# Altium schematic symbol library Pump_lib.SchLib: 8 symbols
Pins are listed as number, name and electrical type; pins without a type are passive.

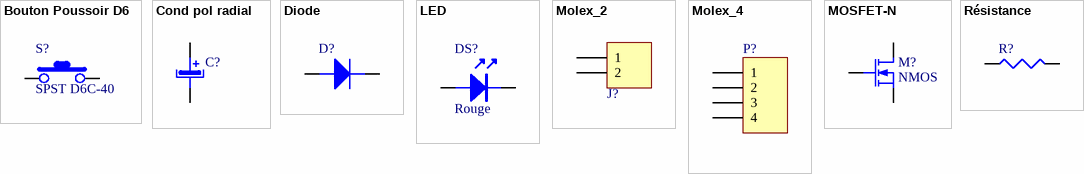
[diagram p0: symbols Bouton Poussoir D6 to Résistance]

## Bouton Poussoir D6
designator S?  Type: SPST D6C-40
Bouton poussoir; Manufacturer: ITT CANON
footprint BP-D6 SPST (Footprint not found)
pins: 1, 2

## Cond pol radial
designator C?
Condensateur polatisé; Type: Condensateur polarisé debout
footprint CAPPR1.27-1.7x2.8 (Capacitor, Radial, Tantalum; Body 1.7 x 2.8 mm (Dia.xH max); Pin Spacing 1.27 mm (typ))
footprint CAPPR1.5-4x5 (Capacitor, Electrolytic, Radial; Body 4 x 5 mm (Dia.xH typ); Pin Spacing 1.5 mm (typ))
footprint CAPPR2-5x6.8 (Capacitor, Electrolytic, Radial; Body 5 x 6.8 mm (Dia.xH typ); Pin Spacing 2 mm (typ))
footprint CAPPR5-5x5 (Capacitor, Electrolytic, Radial; Body 5 x 5 mm (Dia.xH typ); Pin Spacing 5 mm (typ))
footprint CAPPR7.5-16x35 (Capacitor, Electrolytic, Radial; Body 16 x 35 mm (Dia.xH typ); Pin Spacing 7.5 mm (typ))
pins: 1 +, 2 -
2 alternate drawings of the same symbol

## Diode
designator D?
Diode; Type: Diode standard
simulation model DIODE (Diode)
footprint DIO7.1-3.9x1.9 (Diode, Axial; Body 3.8 x 1.9 mm (LxDia. max), Lead Dia. 0.53 mm (max))
footprint DIO7.8-4.6x2 (Diode, Axial; Body 4.6 x 1.9 mm (LxDia. max), Lead Dia. 0.53 mm (max))
footprint DIO10.2-7x2.7 (Diode, Axial; Body 7 x 2.7 mm (LxDia. max), Lead Dia. 0.53 mm (max))
footprint DIO10.46-5.3x2.8 (Diode, Axial; Body 5.2 x 2.7 mm (LxDia. max), Lead Dia. 0.86 mm (max))
footprint DIO18.84-9.6x5.6 (Diode, Axial; Body 9.5 x 5.6 mm (LxDia. max), Lead Dia. 1.32 mm (max))
footprint DIODE-0.4 (Tunnel Diode - Dependent Source Model; 2 Leads)
footprint DIODE-0.7 (Zener Diode; 2 Leads)
pins: 1 A, 2 K

## LED
designator DS?  Color: Rouge
LED
footprint LED 0.1 (Led Verticale)
pins: 1 A, 2 K

## Molex_2
designator J?
Header, 2-pin
footprint Header_2Ecam
pins: 1, 2

## Molex_4
designator P?
Header, 4-Pin
footprint Header4_ecam
pins: 1, 2, 3, 4

## MOSFET-N
designator M?  value NMOS
MOSFET
footprint TO-92 (TO, Flat Index; 3 In-Line, Axial Leads; Body Dia. 4.6mm; Leads 0.48 x 0.43 mm (max) NOT ECAM RULES)
footprint TO-220 V (TO-220 Vertical)
pins: D, G, S
1 alternate drawing of the same symbol

## Résistance
designator R?
Résistance standard
footprint AXIAL-0.4 (Resistor; 2 Leads)
pins: 1, 2
3 alternate drawings of the same symbol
